// Mitsubishi GX Works2 project: PJT07_13_PLC(20220517_01)   PLC: Q03UDV

FUNCTION_BLOCK Alarm_FB
VAR_INPUT
  IB_Alarm : BOOL;  (* 入力@警報発生(0:-/1:発生) *)
END_VAR
VAR
  VT_AlarmDelayTimer : TIMER;  (* 内部@異常入力ﾃﾞｨﾚｲﾀｲﾏ *)
END_VAR
VAR_INPUT
  IW_DelayTimerVal : INT;  (* 入力@ﾃﾞｨﾚｲﾀｲﾏ値 *)
END_VAR
VAR_OUTPUT
  OB_AlarmHolding : BOOL;  (* 出力@ｱﾗｰﾑ自己保持(0:-/1:保持) *)
END_VAR
VAR_INPUT
  IB_AlarmResetPB : BOOL;  (* 入力@警報ﾘｾｯﾄPB(0:-/1:ﾘｾｯﾄ) *)
END_VAR
VAR
  VT_BuzzerStopTimer : TIMER;  (* 内部@ﾌﾞｻﾞｰｽﾄｯﾌﾟﾀｲﾏ *)
END_VAR
VAR_INPUT
  IW_BzStopTVal : INT;  (* 入力@ﾌﾞｻﾞｰｽﾄｯﾌﾟﾀｲﾏ値 *)
END_VAR
VAR
  VB_BuzzerStopFLG : BOOL;  (* 内部@ﾌﾞｻﾞｰｽﾄｯﾌﾟﾃﾞﾊﾞｲｽ(0:-/1:停止) *)
END_VAR
VAR_OUTPUT
  OB_DisplayFLG : BOOL;  (* 出力@ｱﾗｰﾑ表示ﾃﾞﾊﾞｲｽ(0:点滅/1:点灯) *)
END_VAR
VAR_INPUT
  IB_BuzzerStopPB : BOOL;  (* 入力@ﾌﾞｻﾞｰｽﾄｯﾌﾟPB(0:-/1:ｽﾄｯﾌﾟ) *)
END_VAR
VAR_OUTPUT
  OB_BuzzerFLG : BOOL;  (* 出力@ﾌﾞｻﾞｰﾌﾗｸﾞ *)
END_VAR
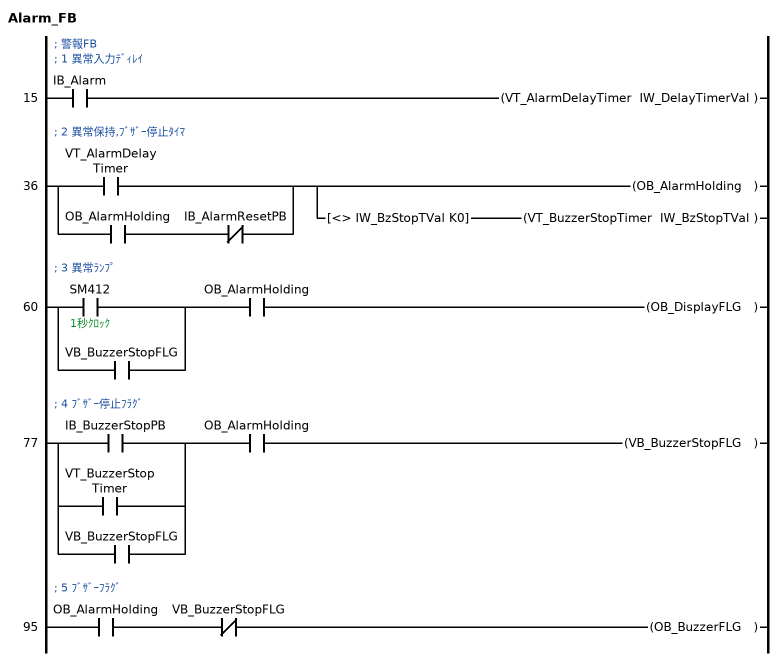
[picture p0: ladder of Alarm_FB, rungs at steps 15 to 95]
; 警報FB
; 1 異常入力ﾃﾞｨﾚｲ
15    LD      IB_Alarm
      OUT     VT_AlarmDelayTimer IW_DelayTimerVal
; 2 異常保持,ﾌﾞｻﾞｰ停止ﾀｲﾏ
36    LD      VT_AlarmDelayTimer
      LD      OB_AlarmHolding
      ANI     IB_AlarmResetPB
      ORB
      OUT     OB_AlarmHolding
      AND<>   IW_BzStopTVal K0
      OUT     VT_BuzzerStopTimer IW_BzStopTVal
; 3 異常ﾗﾝﾌﾟ
60    LD      SM412  ; 1秒ｸﾛｯｸ
      OR      VB_BuzzerStopFLG
      AND     OB_AlarmHolding
      OUT     OB_DisplayFLG
; 4 ﾌﾞｻﾞｰ停止ﾌﾗｸﾞ
77    LD      IB_BuzzerStopPB
      OR      VT_BuzzerStopTimer
      OR      VB_BuzzerStopFLG
      AND     OB_AlarmHolding
      OUT     VB_BuzzerStopFLG
; 5 ﾌﾞｻﾞｰﾌﾗｸﾞ
95    LD      OB_AlarmHolding
      ANI     VB_BuzzerStopFLG
      OUT     OB_BuzzerFLG
END_FUNCTION_BLOCK

PROGRAM 11_Alarm
VAR
  Alarm_FB_1 : Alarm_FB;
  Alarm_FB_2 : Alarm_FB;
END_VAR
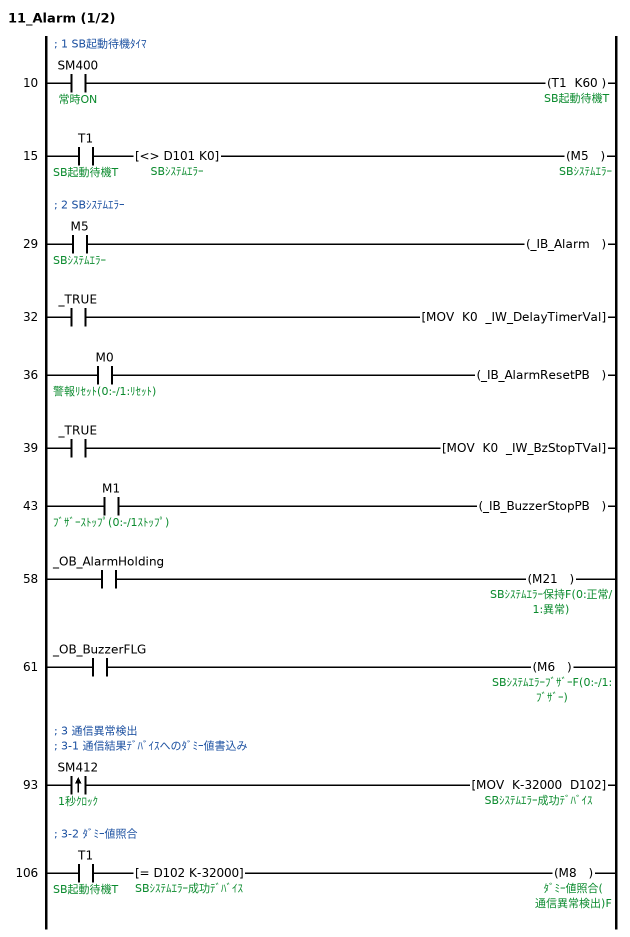
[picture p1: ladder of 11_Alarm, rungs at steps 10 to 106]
; 1 SB起動待機ﾀｲﾏ
10    LD      SM400  ; 常時ON
      OUT     T1 K60  ; SB起動待機T
15    LD      T1  ; SB起動待機T
      AND<>   D101 K0  ; SBｼｽﾃﾑｴﾗｰ
      OUT     M5  ; SBｼｽﾃﾑｴﾗｰ
; FB BLK START Alarm_FB(Alarm_FB_1)
; 2 SBｼｽﾃﾑｴﾗｰ
29    LD      M5  ; SBｼｽﾃﾑｴﾗｰ
      OUT     _IB_Alarm
32    LD      _TRUE
      MOV     K0 _IW_DelayTimerVal
36    LD      M0  ; 警報ﾘｾｯﾄ(0:-/1:ﾘｾｯﾄ)
      OUT     _IB_AlarmResetPB
39    LD      _TRUE
      MOV     K0 _IW_BzStopTVal
43    LD      M1  ; ﾌﾞｻﾞｰｽﾄｯﾌﾟ(0:-/1ｽﾄｯﾌﾟ)
      OUT     _IB_BuzzerStopPB
; FB START
; FB_NAME Alarm_FB
; INSTANCE_NAME Alarm_FB_1
; FB IN_B:IB_Alarm
; FB OUT_OB_AlarmHolding:B
; FB IN_W:IW_DelayTimerVal
; FB OUT_OB_DisplayFLG:B
; FB IN_B:IB_AlarmResetPB
; FB OUT_OB_BuzzerFLG:B
; FB IN_W:IW_BzStopTVal
; FB IN_B:IB_BuzzerStopPB
; FB END
58    LD      _OB_AlarmHolding
      OUT     M21  ; SBｼｽﾃﾑｴﾗｰ保持F(0:正常/1:異常)
61    LD      _OB_BuzzerFLG
      OUT     M6  ; SBｼｽﾃﾑｴﾗｰﾌﾞｻﾞｰF(0:-/1:ﾌﾞｻﾞｰ)
; FB BLK END
; 3 通信異常検出
; 3-1 通信結果ﾃﾞﾊﾞｲｽへのﾀﾞﾐｰ値書込み
93    LDP     SM412  ; 1秒ｸﾛｯｸ
      MOV     K-32000 D102  ; SBｼｽﾃﾑｴﾗｰ成功ﾃﾞﾊﾞｲｽ
; 3-2 ﾀﾞﾐｰ値照合
106   LD      T1  ; SB起動待機T
      AND=    D102 K-32000  ; SBｼｽﾃﾑｴﾗｰ成功ﾃﾞﾊﾞｲｽ
      OUT     M8  ; ﾀﾞﾐｰ値照合(通信異常検出)F
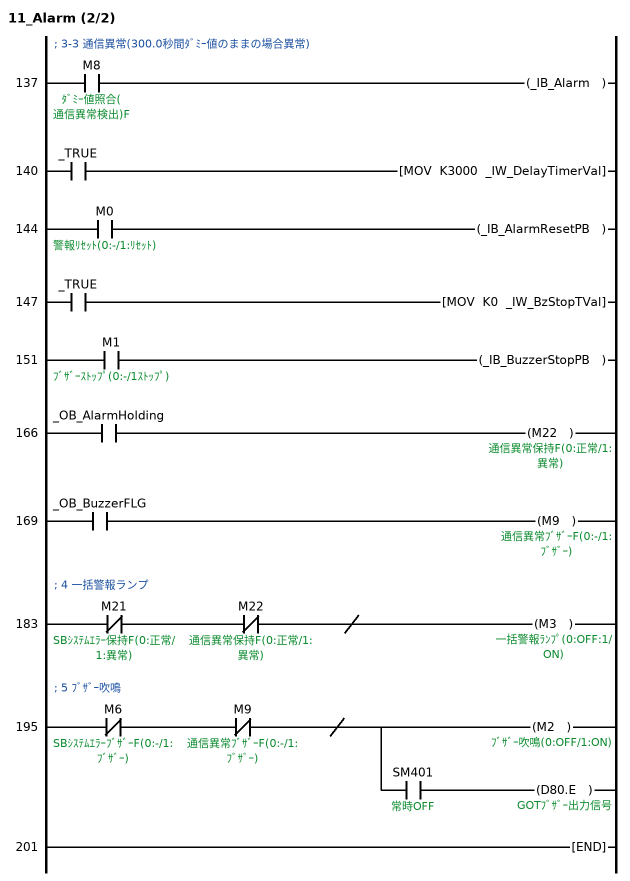
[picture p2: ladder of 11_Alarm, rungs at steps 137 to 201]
; FB BLK START Alarm_FB(Alarm_FB_2)
; 3-3 通信異常(300.0秒間ﾀﾞﾐｰ値のままの場合異常)
137   LD      M8  ; ﾀﾞﾐｰ値照合(通信異常検出)F
      OUT     _IB_Alarm
140   LD      _TRUE
      MOV     K3000 _IW_DelayTimerVal
144   LD      M0  ; 警報ﾘｾｯﾄ(0:-/1:ﾘｾｯﾄ)
      OUT     _IB_AlarmResetPB
147   LD      _TRUE
      MOV     K0 _IW_BzStopTVal
151   LD      M1  ; ﾌﾞｻﾞｰｽﾄｯﾌﾟ(0:-/1ｽﾄｯﾌﾟ)
      OUT     _IB_BuzzerStopPB
; FB START
; FB_NAME Alarm_FB
; INSTANCE_NAME Alarm_FB_2
; FB IN_B:IB_Alarm
; FB OUT_OB_AlarmHolding:B
; FB IN_W:IW_DelayTimerVal
; FB OUT_OB_DisplayFLG:B
; FB IN_B:IB_AlarmResetPB
; FB OUT_OB_BuzzerFLG:B
; FB IN_W:IW_BzStopTVal
; FB IN_B:IB_BuzzerStopPB
; FB END
166   LD      _OB_AlarmHolding
      OUT     M22  ; 通信異常保持F(0:正常/1:異常)
169   LD      _OB_BuzzerFLG
      OUT     M9  ; 通信異常ﾌﾞｻﾞｰF(0:-/1:ﾌﾞｻﾞｰ)
; FB BLK END
; 4 一括警報ランプ
183   LDI     M21  ; SBｼｽﾃﾑｴﾗｰ保持F(0:正常/1:異常)
      ANI     M22  ; 通信異常保持F(0:正常/1:異常)
      INV
      OUT     M3  ; 一括警報ﾗﾝﾌﾟ(0:OFF:1/ON)
; 5 ﾌﾞｻﾞｰ吹鳴
195   LDI     M6  ; SBｼｽﾃﾑｴﾗｰﾌﾞｻﾞｰF(0:-/1:ﾌﾞｻﾞｰ)
      ANI     M9  ; 通信異常ﾌﾞｻﾞｰF(0:-/1:ﾌﾞｻﾞｰ)
      INV
      OUT     M2  ; ﾌﾞｻﾞｰ吹鳴(0:OFF/1:ON)
      AND     SM401  ; 常時OFF
      OUT     D80.E  ; GOTﾌﾞｻﾞｰ出力信号
201   END
END_PROGRAM

PROGRAM 02_#2  // SB_Initial
VAR
  __IST_553ac48fffaf4984 : I+ST_553ac48fffaf4984;
END_VAR
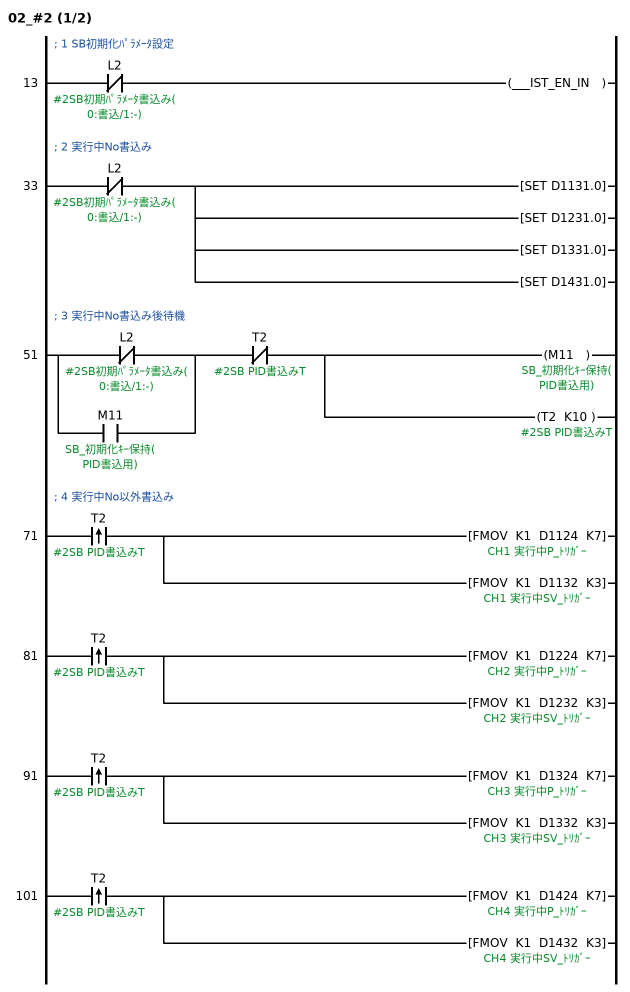
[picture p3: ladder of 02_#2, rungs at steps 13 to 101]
; FB BLK START I+ST_553ac48fffaf4984(__IST_553ac48fffaf4984)
; 1 SB初期化ﾊﾟﾗﾒｰﾀ設定
13    LDI     L2  ; #2SB初期ﾊﾟﾗﾒｰﾀ書込み(0:書込/1:-)
      OUT     ___IST_EN_IN
; FB START
; FB_NAME I+ST_553ac48fffaf4984
; INSTANCE_NAME __IST_553ac48fffaf4984
; FB IN_B:__IST_EN_IN
; FB OUT___IST_EN_OUT:B
; FB END
; FB BLK END
; 2 実行中No書込み
33    LDI     L2  ; #2SB初期ﾊﾟﾗﾒｰﾀ書込み(0:書込/1:-)
      SET     D1131.0
      SET     D1231.0
      SET     D1331.0
      SET     D1431.0
; 3 実行中No書込み後待機
51    LDI     L2  ; #2SB初期ﾊﾟﾗﾒｰﾀ書込み(0:書込/1:-)
      OR      M11  ; SB_初期化ｷｰ保持(PID書込用)
      ANI     T2  ; #2SB PID書込みT
      OUT     M11  ; SB_初期化ｷｰ保持(PID書込用)
      OUT     T2 K10  ; #2SB PID書込みT
; 4 実行中No以外書込み
71    LDP     T2  ; #2SB PID書込みT
      FMOV    K1 D1124 K7  ; CH1 実行中P_ﾄﾘｶﾞｰ
      FMOV    K1 D1132 K3  ; CH1 実行中SV_ﾄﾘｶﾞｰ
81    LDP     T2  ; #2SB PID書込みT
      FMOV    K1 D1224 K7  ; CH2 実行中P_ﾄﾘｶﾞｰ
      FMOV    K1 D1232 K3  ; CH2 実行中SV_ﾄﾘｶﾞｰ
91    LDP     T2  ; #2SB PID書込みT
      FMOV    K1 D1324 K7  ; CH3 実行中P_ﾄﾘｶﾞｰ
      FMOV    K1 D1332 K3  ; CH3 実行中SV_ﾄﾘｶﾞｰ
101   LDP     T2  ; #2SB PID書込みT
      FMOV    K1 D1424 K7  ; CH4 実行中P_ﾄﾘｶﾞｰ
      FMOV    K1 D1432 K3  ; CH4 実行中SV_ﾄﾘｶﾞｰ
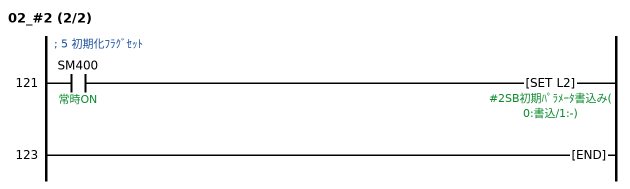
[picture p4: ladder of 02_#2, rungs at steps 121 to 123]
; 5 初期化ﾌﾗｸﾞｾｯﾄ
121   LD      SM400  ; 常時ON
      SET     L2  ; #2SB初期ﾊﾟﾗﾒｰﾀ書込み(0:書込/1:-)
123   END
END_PROGRAM

PROGRAM 22_#2  // SB100
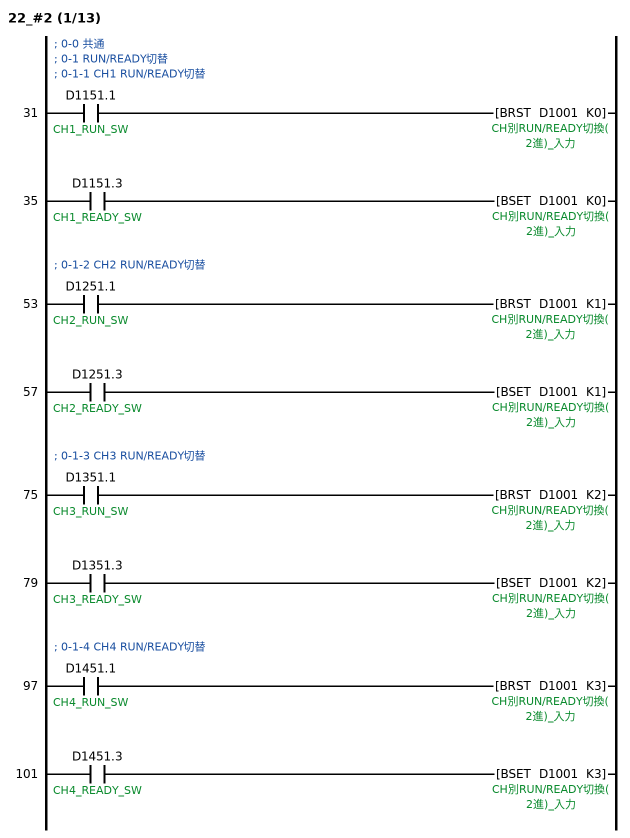
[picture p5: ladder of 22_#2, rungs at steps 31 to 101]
; 0-0 共通
; 0-1 RUN/READY切替
; 0-1-1 CH1 RUN/READY切替
31    LD      D1151.1  ; CH1_RUN_SW
      BRST    D1001 K0  ; CH別RUN/READY切換(2進)_入力
35    LD      D1151.3  ; CH1_READY_SW
      BSET    D1001 K0
; 0-1-2 CH2 RUN/READY切替
53    LD      D1251.1  ; CH2_RUN_SW
      BRST    D1001 K1
57    LD      D1251.3  ; CH2_READY_SW
      BSET    D1001 K1
; 0-1-3 CH3 RUN/READY切替
75    LD      D1351.1  ; CH3_RUN_SW
      BRST    D1001 K2
79    LD      D1351.3  ; CH3_READY_SW
      BSET    D1001 K2
; 0-1-4 CH4 RUN/READY切替
97    LD      D1451.1  ; CH4_RUN_SW
      BRST    D1001 K3
101   LD      D1451.3  ; CH4_READY_SW
      BSET    D1001 K3
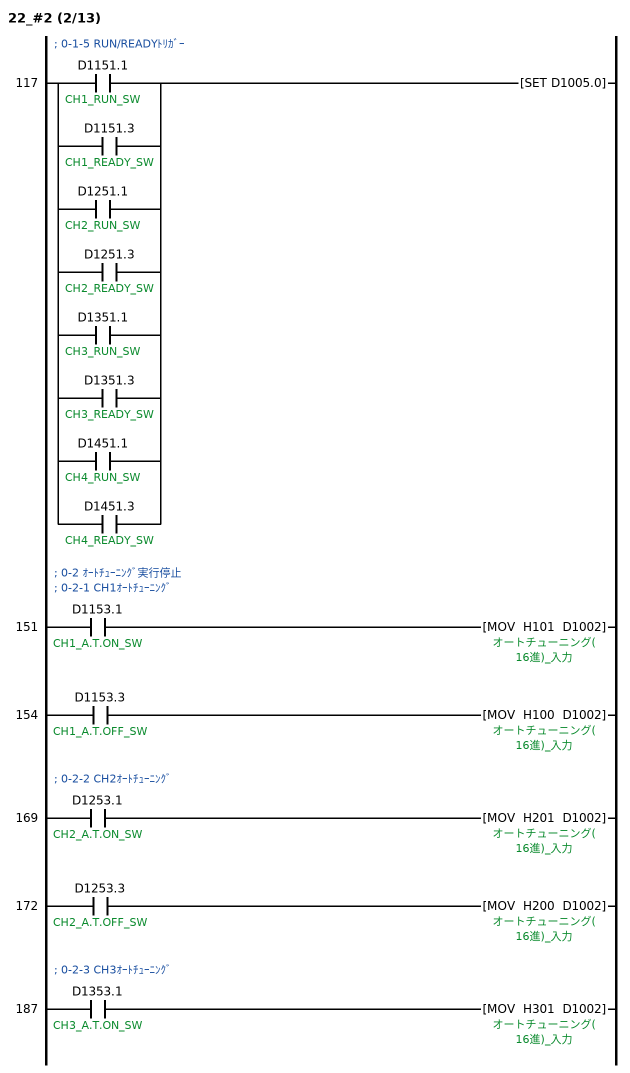
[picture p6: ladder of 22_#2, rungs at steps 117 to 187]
; 0-1-5 RUN/READYﾄﾘｶﾞｰ
117   LD      D1151.1  ; CH1_RUN_SW
      OR      D1151.3  ; CH1_READY_SW
      OR      D1251.1  ; CH2_RUN_SW
      OR      D1251.3  ; CH2_READY_SW
      OR      D1351.1  ; CH3_RUN_SW
      OR      D1351.3  ; CH3_READY_SW
      OR      D1451.1  ; CH4_RUN_SW
      OR      D1451.3  ; CH4_READY_SW
      SET     D1005.0
; 0-2 ｵｰﾄﾁｭｰﾆﾝｸﾞ実行停止
; 0-2-1 CH1ｵｰﾄﾁｭｰﾆﾝｸﾞ
151   LD      D1153.1  ; CH1_A.T.ON_SW
      MOV     H101 D1002  ; オートチューニング(16進)_入力
154   LD      D1153.3  ; CH1_A.T.OFF_SW
      MOV     H100 D1002
; 0-2-2 CH2ｵｰﾄﾁｭｰﾆﾝｸﾞ
169   LD      D1253.1  ; CH2_A.T.ON_SW
      MOV     H201 D1002
172   LD      D1253.3  ; CH2_A.T.OFF_SW
      MOV     H200 D1002
; 0-2-3 CH3ｵｰﾄﾁｭｰﾆﾝｸﾞ
187   LD      D1353.1  ; CH3_A.T.ON_SW
      MOV     H301 D1002
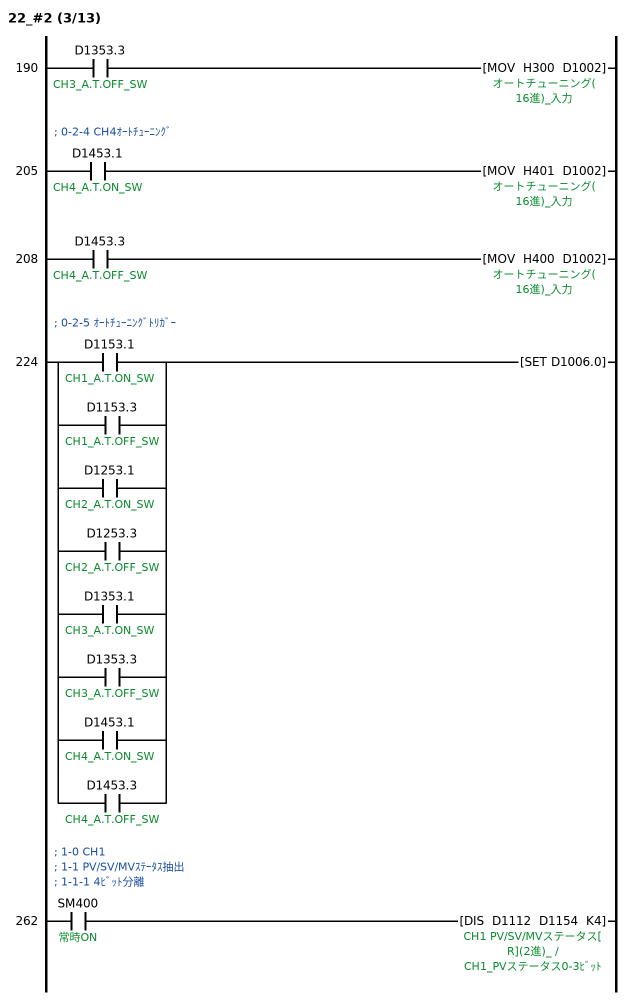
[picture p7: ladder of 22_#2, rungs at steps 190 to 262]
190   LD      D1353.3  ; CH3_A.T.OFF_SW
      MOV     H300 D1002
; 0-2-4 CH4ｵｰﾄﾁｭｰﾆﾝｸﾞ
205   LD      D1453.1  ; CH4_A.T.ON_SW
      MOV     H401 D1002
208   LD      D1453.3  ; CH4_A.T.OFF_SW
      MOV     H400 D1002
; 0-2-5 ｵｰﾄﾁｭｰﾆﾝｸﾞﾄﾘｶﾞｰ
224   LD      D1153.1  ; CH1_A.T.ON_SW
      OR      D1153.3  ; CH1_A.T.OFF_SW
      OR      D1253.1  ; CH2_A.T.ON_SW
      OR      D1253.3  ; CH2_A.T.OFF_SW
      OR      D1353.1  ; CH3_A.T.ON_SW
      OR      D1353.3  ; CH3_A.T.OFF_SW
      OR      D1453.1  ; CH4_A.T.ON_SW
      OR      D1453.3  ; CH4_A.T.OFF_SW
      SET     D1006.0
; 1-0 CH1
; 1-1 PV/SV/MVｽﾃｰﾀｽ抽出
; 1-1-1 4ﾋﾞｯﾄ分離
262   LD      SM400  ; 常時ON
      DIS     D1112 D1154 K4  ; CH1 PV/SV/MVステータス[R](2進)_ / CH1_PVステータス0-3ﾋﾞｯﾄ
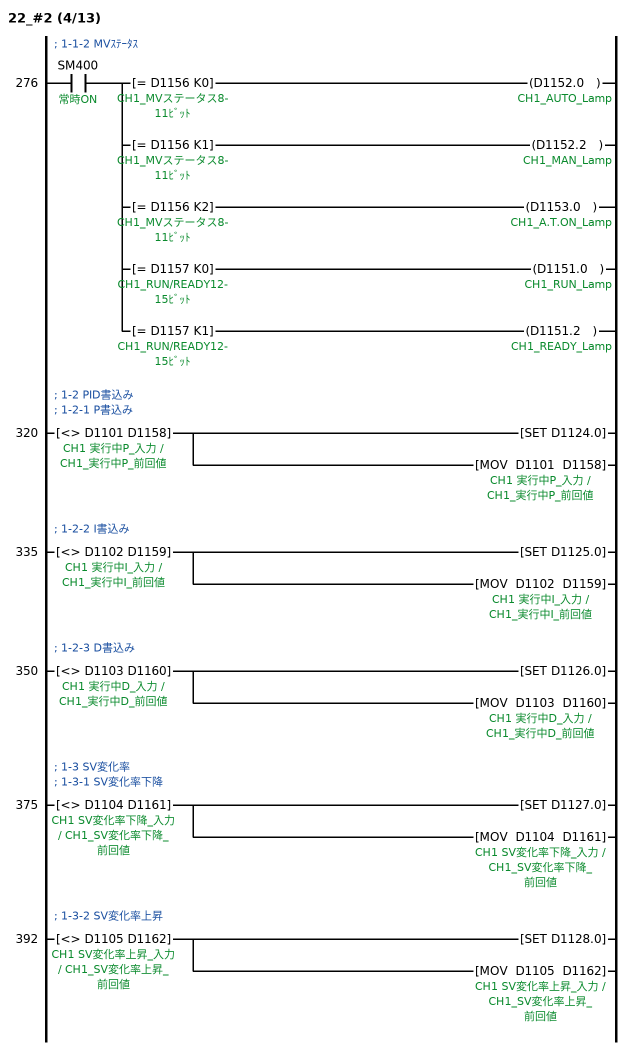
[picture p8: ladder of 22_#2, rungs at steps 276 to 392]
; 1-1-2 MVｽﾃｰﾀｽ
276   LD      SM400  ; 常時ON
      MPS
      AND=    D1156 K0  ; CH1_MVステータス8-11ﾋﾞｯﾄ
      OUT     D1152.0  ; CH1_AUTO_Lamp
      MRD
      AND=    D1156 K1  ; CH1_MVステータス8-11ﾋﾞｯﾄ
      OUT     D1152.2  ; CH1_MAN_Lamp
      MRD
      AND=    D1156 K2  ; CH1_MVステータス8-11ﾋﾞｯﾄ
      OUT     D1153.0  ; CH1_A.T.ON_Lamp
      MRD
      AND=    D1157 K0  ; CH1_RUN/READY12-15ﾋﾞｯﾄ
      OUT     D1151.0  ; CH1_RUN_Lamp
      MPP
      AND=    D1157 K1  ; CH1_RUN/READY12-15ﾋﾞｯﾄ
      OUT     D1151.2  ; CH1_READY_Lamp
; 1-2 PID書込み
; 1-2-1 P書込み
320   LD<>    D1101 D1158  ; CH1 実行中P_入力 / CH1_実行中P_前回値
      SET     D1124.0
      MOV     D1101 D1158
; 1-2-2 I書込み
335   LD<>    D1102 D1159  ; CH1 実行中I_入力 / CH1_実行中I_前回値
      SET     D1125.0
      MOV     D1102 D1159
; 1-2-3 D書込み
350   LD<>    D1103 D1160  ; CH1 実行中D_入力 / CH1_実行中D_前回値
      SET     D1126.0
      MOV     D1103 D1160
; 1-3 SV変化率
; 1-3-1 SV変化率下降
375   LD<>    D1104 D1161  ; CH1 SV変化率下降_入力 / CH1_SV変化率下降_前回値
      SET     D1127.0
      MOV     D1104 D1161
; 1-3-2 SV変化率上昇
392   LD<>    D1105 D1162  ; CH1 SV変化率上昇_入力 / CH1_SV変化率上昇_前回値
      SET     D1128.0
      MOV     D1105 D1162
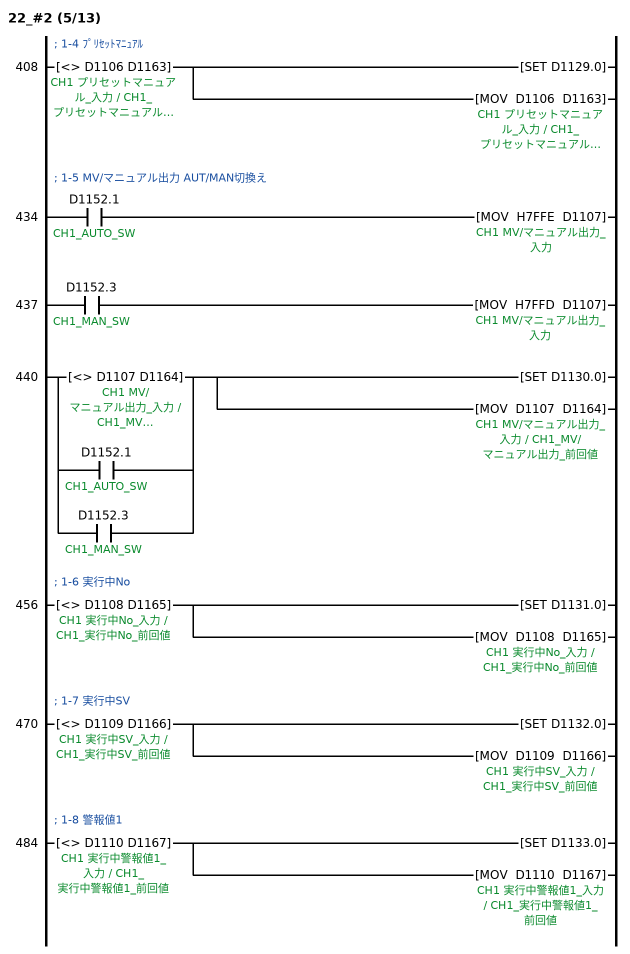
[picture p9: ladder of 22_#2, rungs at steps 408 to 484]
; 1-4 ﾌﾟﾘｾｯﾄﾏﾆｭｱﾙ
408   LD<>    D1106 D1163  ; CH1 プリセットマニュアル_入力 / CH1_プリセットマニュアル_前回値
      SET     D1129.0
      MOV     D1106 D1163
; 1-5 MV/マニュアル出力 AUT/MAN切換え
434   LD      D1152.1  ; CH1_AUTO_SW
      MOV     H7FFE D1107  ; CH1 MV/マニュアル出力_入力
437   LD      D1152.3  ; CH1_MAN_SW
      MOV     H7FFD D1107
440   LD<>    D1107 D1164  ; CH1 MV/マニュアル出力_入力 / CH1_MV/マニュアル出力_前回値
      OR      D1152.1  ; CH1_AUTO_SW
      OR      D1152.3  ; CH1_MAN_SW
      SET     D1130.0
      MOV     D1107 D1164
; 1-6 実行中No
456   LD<>    D1108 D1165  ; CH1 実行中No_入力 / CH1_実行中No_前回値
      SET     D1131.0
      MOV     D1108 D1165
; 1-7 実行中SV
470   LD<>    D1109 D1166  ; CH1 実行中SV_入力 / CH1_実行中SV_前回値
      SET     D1132.0
      MOV     D1109 D1166
; 1-8 警報値1
484   LD<>    D1110 D1167  ; CH1 実行中警報値1_入力 / CH1_実行中警報値1_前回値
      SET     D1133.0
      MOV     D1110 D1167
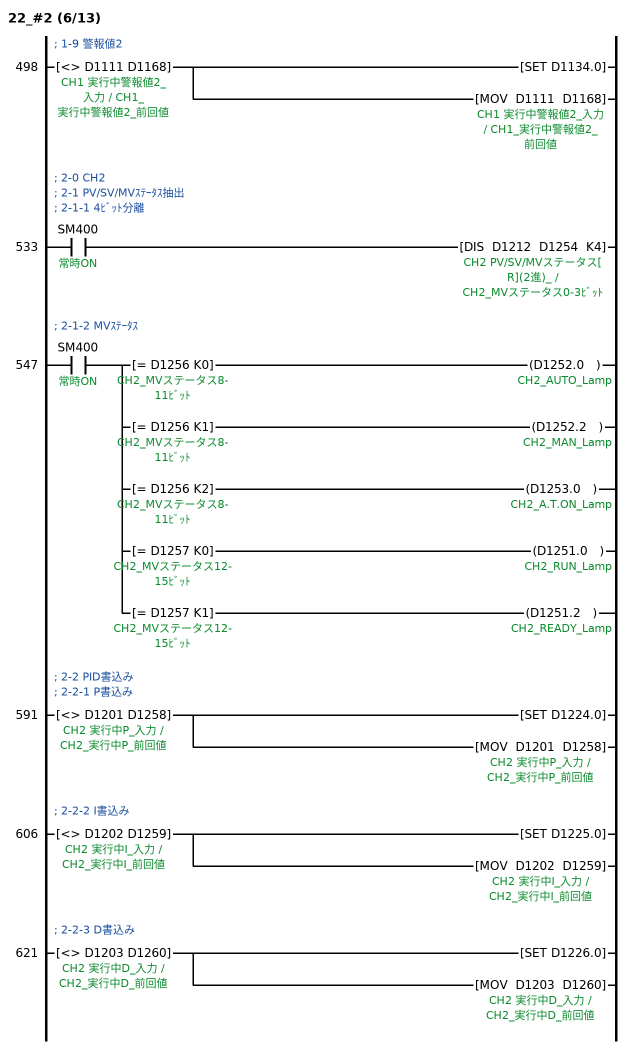
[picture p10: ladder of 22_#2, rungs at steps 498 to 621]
; 1-9 警報値2
498   LD<>    D1111 D1168  ; CH1 実行中警報値2_入力 / CH1_実行中警報値2_前回値
      SET     D1134.0
      MOV     D1111 D1168
; 2-0 CH2
; 2-1 PV/SV/MVｽﾃｰﾀｽ抽出
; 2-1-1 4ﾋﾞｯﾄ分離
533   LD      SM400  ; 常時ON
      DIS     D1212 D1254 K4  ; CH2 PV/SV/MVステータス[R](2進)_ / CH2_MVステータス0-3ﾋﾞｯﾄ
; 2-1-2 MVｽﾃｰﾀｽ
547   LD      SM400  ; 常時ON
      MPS
      AND=    D1256 K0  ; CH2_MVステータス8-11ﾋﾞｯﾄ
      OUT     D1252.0  ; CH2_AUTO_Lamp
      MRD
      AND=    D1256 K1  ; CH2_MVステータス8-11ﾋﾞｯﾄ
      OUT     D1252.2  ; CH2_MAN_Lamp
      MRD
      AND=    D1256 K2  ; CH2_MVステータス8-11ﾋﾞｯﾄ
      OUT     D1253.0  ; CH2_A.T.ON_Lamp
      MRD
      AND=    D1257 K0  ; CH2_MVステータス12-15ﾋﾞｯﾄ
      OUT     D1251.0  ; CH2_RUN_Lamp
      MPP
      AND=    D1257 K1  ; CH2_MVステータス12-15ﾋﾞｯﾄ
      OUT     D1251.2  ; CH2_READY_Lamp
; 2-2 PID書込み
; 2-2-1 P書込み
591   LD<>    D1201 D1258  ; CH2 実行中P_入力 / CH2_実行中P_前回値
      SET     D1224.0
      MOV     D1201 D1258
; 2-2-2 I書込み
606   LD<>    D1202 D1259  ; CH2 実行中I_入力 / CH2_実行中I_前回値
      SET     D1225.0
      MOV     D1202 D1259
; 2-2-3 D書込み
621   LD<>    D1203 D1260  ; CH2 実行中D_入力 / CH2_実行中D_前回値
      SET     D1226.0
      MOV     D1203 D1260
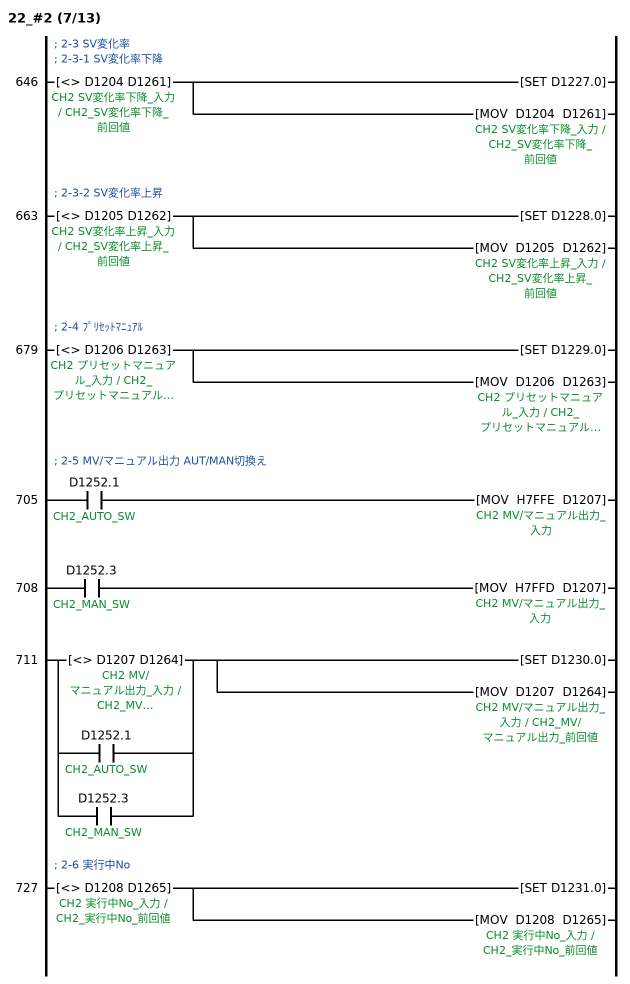
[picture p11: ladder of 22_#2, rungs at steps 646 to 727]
; 2-3 SV変化率
; 2-3-1 SV変化率下降
646   LD<>    D1204 D1261  ; CH2 SV変化率下降_入力 / CH2_SV変化率下降_前回値
      SET     D1227.0
      MOV     D1204 D1261
; 2-3-2 SV変化率上昇
663   LD<>    D1205 D1262  ; CH2 SV変化率上昇_入力 / CH2_SV変化率上昇_前回値
      SET     D1228.0
      MOV     D1205 D1262
; 2-4 ﾌﾟﾘｾｯﾄﾏﾆｭｱﾙ
679   LD<>    D1206 D1263  ; CH2 プリセットマニュアル_入力 / CH2_プリセットマニュアル_前回値
      SET     D1229.0
      MOV     D1206 D1263
; 2-5 MV/マニュアル出力 AUT/MAN切換え
705   LD      D1252.1  ; CH2_AUTO_SW
      MOV     H7FFE D1207  ; CH2 MV/マニュアル出力_入力
708   LD      D1252.3  ; CH2_MAN_SW
      MOV     H7FFD D1207
711   LD<>    D1207 D1264  ; CH2 MV/マニュアル出力_入力 / CH2_MV/マニュアル出力_前回値
      OR      D1252.1  ; CH2_AUTO_SW
      OR      D1252.3  ; CH2_MAN_SW
      SET     D1230.0
      MOV     D1207 D1264
; 2-6 実行中No
727   LD<>    D1208 D1265  ; CH2 実行中No_入力 / CH2_実行中No_前回値
      SET     D1231.0
      MOV     D1208 D1265
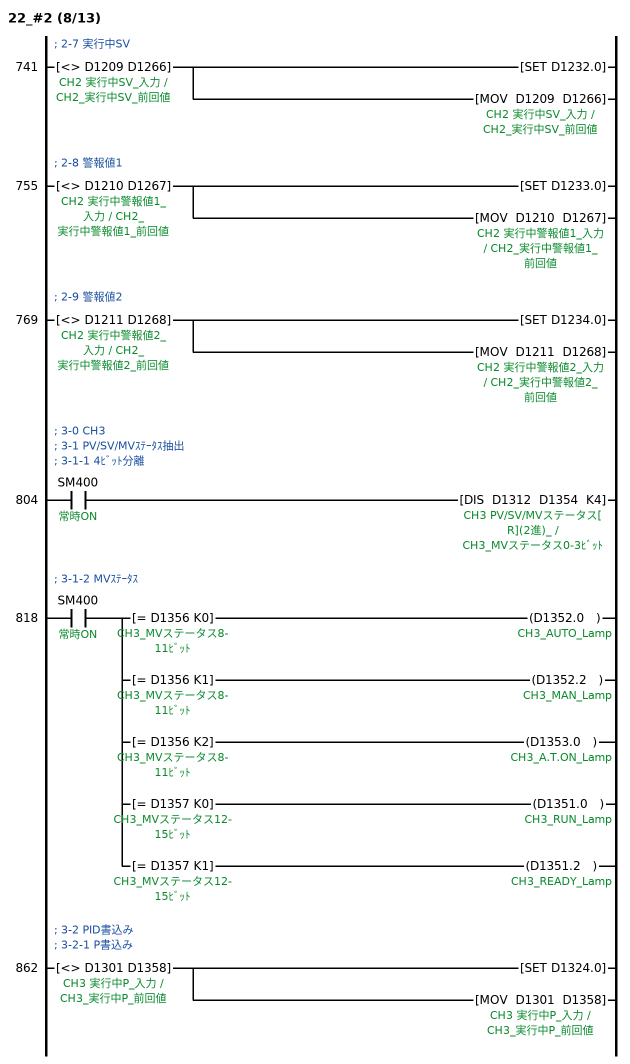
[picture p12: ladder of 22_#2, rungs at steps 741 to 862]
; 2-7 実行中SV
741   LD<>    D1209 D1266  ; CH2 実行中SV_入力 / CH2_実行中SV_前回値
      SET     D1232.0
      MOV     D1209 D1266
; 2-8 警報値1
755   LD<>    D1210 D1267  ; CH2 実行中警報値1_入力 / CH2_実行中警報値1_前回値
      SET     D1233.0
      MOV     D1210 D1267
; 2-9 警報値2
769   LD<>    D1211 D1268  ; CH2 実行中警報値2_入力 / CH2_実行中警報値2_前回値
      SET     D1234.0
      MOV     D1211 D1268
; 3-0 CH3
; 3-1 PV/SV/MVｽﾃｰﾀｽ抽出
; 3-1-1 4ﾋﾞｯﾄ分離
804   LD      SM400  ; 常時ON
      DIS     D1312 D1354 K4  ; CH3 PV/SV/MVステータス[R](2進)_ / CH3_MVステータス0-3ﾋﾞｯﾄ
; 3-1-2 MVｽﾃｰﾀｽ
818   LD      SM400  ; 常時ON
      MPS
      AND=    D1356 K0  ; CH3_MVステータス8-11ﾋﾞｯﾄ
      OUT     D1352.0  ; CH3_AUTO_Lamp
      MRD
      AND=    D1356 K1  ; CH3_MVステータス8-11ﾋﾞｯﾄ
      OUT     D1352.2  ; CH3_MAN_Lamp
      MRD
      AND=    D1356 K2  ; CH3_MVステータス8-11ﾋﾞｯﾄ
      OUT     D1353.0  ; CH3_A.T.ON_Lamp
      MRD
      AND=    D1357 K0  ; CH3_MVステータス12-15ﾋﾞｯﾄ
      OUT     D1351.0  ; CH3_RUN_Lamp
      MPP
      AND=    D1357 K1  ; CH3_MVステータス12-15ﾋﾞｯﾄ
      OUT     D1351.2  ; CH3_READY_Lamp
; 3-2 PID書込み
; 3-2-1 P書込み
862   LD<>    D1301 D1358  ; CH3 実行中P_入力 / CH3_実行中P_前回値
      SET     D1324.0
      MOV     D1301 D1358
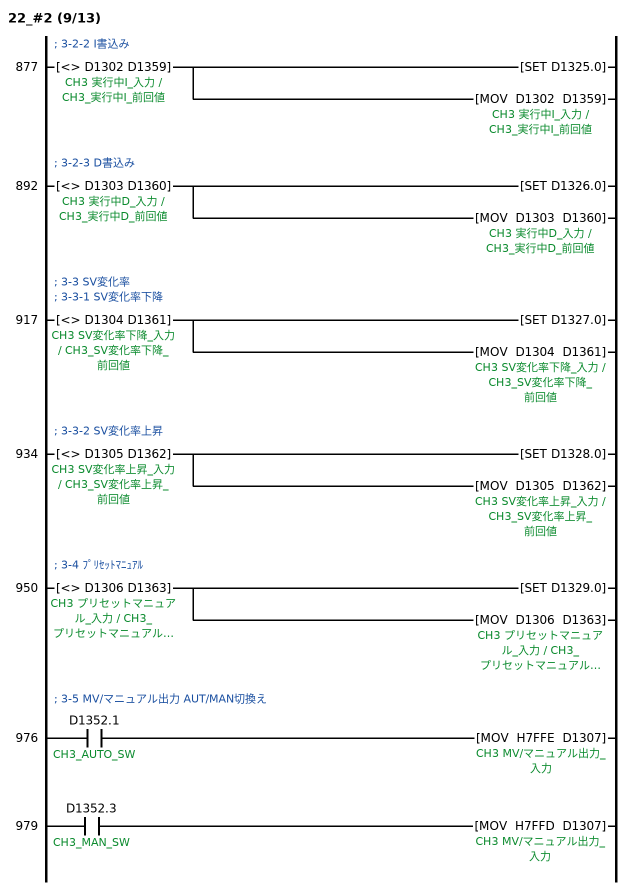
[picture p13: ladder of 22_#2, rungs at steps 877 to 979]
; 3-2-2 I書込み
877   LD<>    D1302 D1359  ; CH3 実行中I_入力 / CH3_実行中I_前回値
      SET     D1325.0
      MOV     D1302 D1359
; 3-2-3 D書込み
892   LD<>    D1303 D1360  ; CH3 実行中D_入力 / CH3_実行中D_前回値
      SET     D1326.0
      MOV     D1303 D1360
; 3-3 SV変化率
; 3-3-1 SV変化率下降
917   LD<>    D1304 D1361  ; CH3 SV変化率下降_入力 / CH3_SV変化率下降_前回値
      SET     D1327.0
      MOV     D1304 D1361
; 3-3-2 SV変化率上昇
934   LD<>    D1305 D1362  ; CH3 SV変化率上昇_入力 / CH3_SV変化率上昇_前回値
      SET     D1328.0
      MOV     D1305 D1362
; 3-4 ﾌﾟﾘｾｯﾄﾏﾆｭｱﾙ
950   LD<>    D1306 D1363  ; CH3 プリセットマニュアル_入力 / CH3_プリセットマニュアル_前回値
      SET     D1329.0
      MOV     D1306 D1363
; 3-5 MV/マニュアル出力 AUT/MAN切換え
976   LD      D1352.1  ; CH3_AUTO_SW
      MOV     H7FFE D1307  ; CH3 MV/マニュアル出力_入力
979   LD      D1352.3  ; CH3_MAN_SW
      MOV     H7FFD D1307
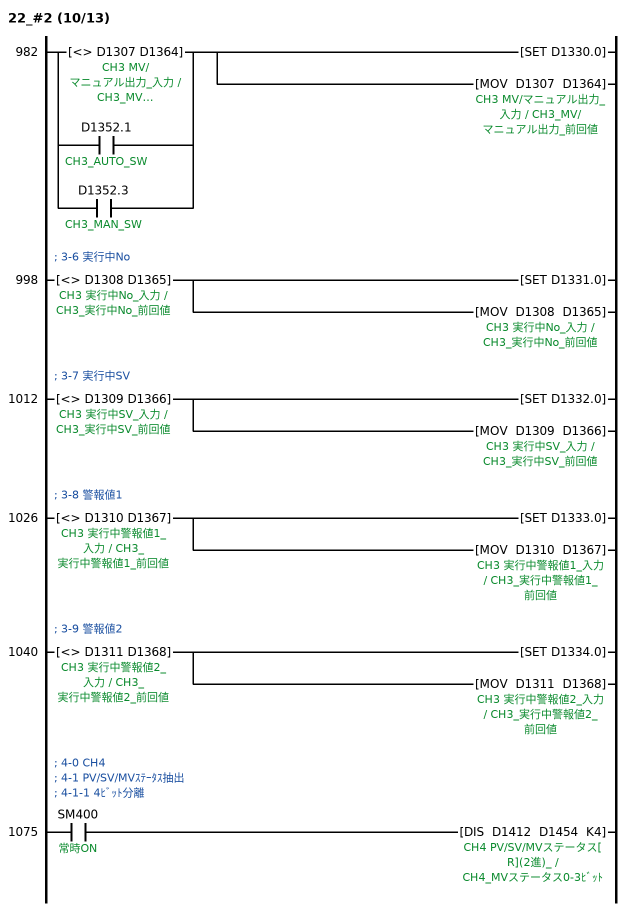
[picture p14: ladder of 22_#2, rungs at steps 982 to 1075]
982   LD<>    D1307 D1364  ; CH3 MV/マニュアル出力_入力 / CH3_MV/マニュアル出力_前回値
      OR      D1352.1  ; CH3_AUTO_SW
      OR      D1352.3  ; CH3_MAN_SW
      SET     D1330.0
      MOV     D1307 D1364
; 3-6 実行中No
998   LD<>    D1308 D1365  ; CH3 実行中No_入力 / CH3_実行中No_前回値
      SET     D1331.0
      MOV     D1308 D1365
; 3-7 実行中SV
1012  LD<>    D1309 D1366  ; CH3 実行中SV_入力 / CH3_実行中SV_前回値
      SET     D1332.0
      MOV     D1309 D1366
; 3-8 警報値1
1026  LD<>    D1310 D1367  ; CH3 実行中警報値1_入力 / CH3_実行中警報値1_前回値
      SET     D1333.0
      MOV     D1310 D1367
; 3-9 警報値2
1040  LD<>    D1311 D1368  ; CH3 実行中警報値2_入力 / CH3_実行中警報値2_前回値
      SET     D1334.0
      MOV     D1311 D1368
; 4-0 CH4
; 4-1 PV/SV/MVｽﾃｰﾀｽ抽出
; 4-1-1 4ﾋﾞｯﾄ分離
1075  LD      SM400  ; 常時ON
      DIS     D1412 D1454 K4  ; CH4 PV/SV/MVステータス[R](2進)_ / CH4_MVステータス0-3ﾋﾞｯﾄ
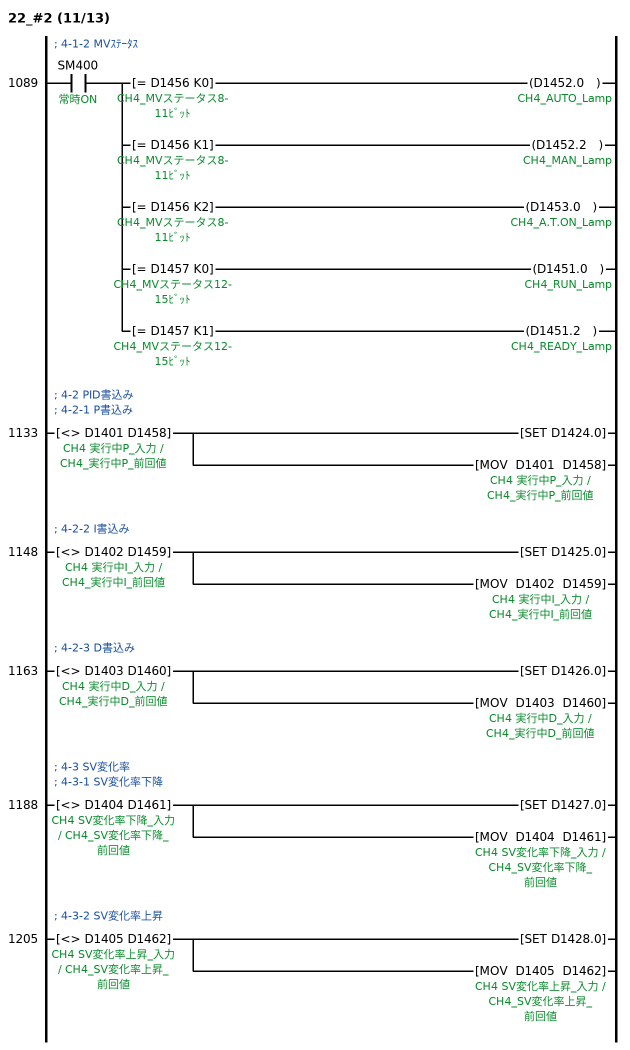
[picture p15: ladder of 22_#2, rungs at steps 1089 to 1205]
; 4-1-2 MVｽﾃｰﾀｽ
1089  LD      SM400  ; 常時ON
      MPS
      AND=    D1456 K0  ; CH4_MVステータス8-11ﾋﾞｯﾄ
      OUT     D1452.0  ; CH4_AUTO_Lamp
      MRD
      AND=    D1456 K1  ; CH4_MVステータス8-11ﾋﾞｯﾄ
      OUT     D1452.2  ; CH4_MAN_Lamp
      MRD
      AND=    D1456 K2  ; CH4_MVステータス8-11ﾋﾞｯﾄ
      OUT     D1453.0  ; CH4_A.T.ON_Lamp
      MRD
      AND=    D1457 K0  ; CH4_MVステータス12-15ﾋﾞｯﾄ
      OUT     D1451.0  ; CH4_RUN_Lamp
      MPP
      AND=    D1457 K1  ; CH4_MVステータス12-15ﾋﾞｯﾄ
      OUT     D1451.2  ; CH4_READY_Lamp
; 4-2 PID書込み
; 4-2-1 P書込み
1133  LD<>    D1401 D1458  ; CH4 実行中P_入力 / CH4_実行中P_前回値
      SET     D1424.0
      MOV     D1401 D1458
; 4-2-2 I書込み
1148  LD<>    D1402 D1459  ; CH4 実行中I_入力 / CH4_実行中I_前回値
      SET     D1425.0
      MOV     D1402 D1459
; 4-2-3 D書込み
1163  LD<>    D1403 D1460  ; CH4 実行中D_入力 / CH4_実行中D_前回値
      SET     D1426.0
      MOV     D1403 D1460
; 4-3 SV変化率
; 4-3-1 SV変化率下降
1188  LD<>    D1404 D1461  ; CH4 SV変化率下降_入力 / CH4_SV変化率下降_前回値
      SET     D1427.0
      MOV     D1404 D1461
; 4-3-2 SV変化率上昇
1205  LD<>    D1405 D1462  ; CH4 SV変化率上昇_入力 / CH4_SV変化率上昇_前回値
      SET     D1428.0
      MOV     D1405 D1462
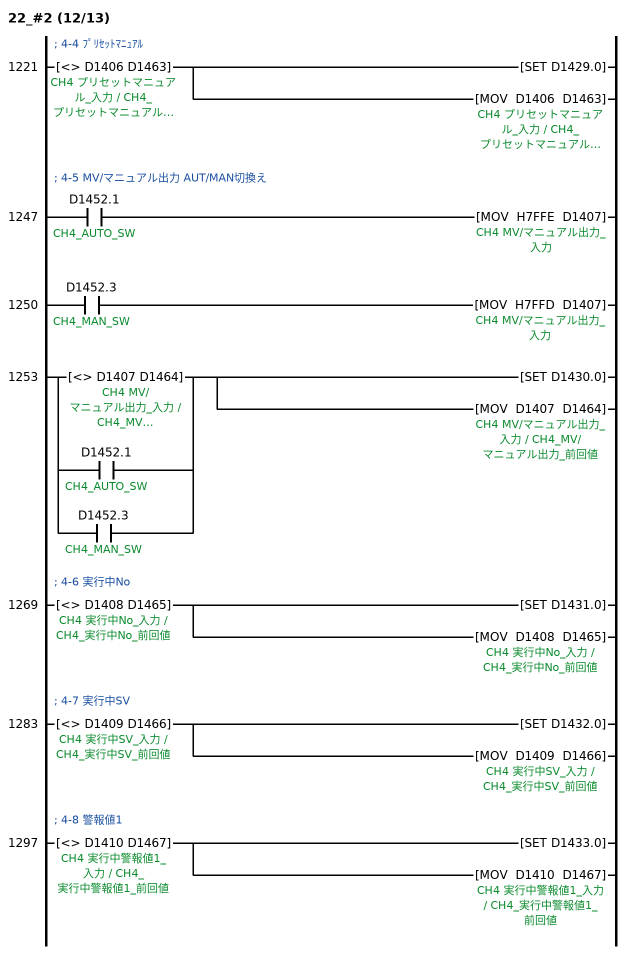
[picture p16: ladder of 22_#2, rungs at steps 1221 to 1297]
; 4-4 ﾌﾟﾘｾｯﾄﾏﾆｭｱﾙ
1221  LD<>    D1406 D1463  ; CH4 プリセットマニュアル_入力 / CH4_プリセットマニュアル_前回値
      SET     D1429.0
      MOV     D1406 D1463
; 4-5 MV/マニュアル出力 AUT/MAN切換え
1247  LD      D1452.1  ; CH4_AUTO_SW
      MOV     H7FFE D1407  ; CH4 MV/マニュアル出力_入力
1250  LD      D1452.3  ; CH4_MAN_SW
      MOV     H7FFD D1407
1253  LD<>    D1407 D1464  ; CH4 MV/マニュアル出力_入力 / CH4_MV/マニュアル出力_前回値
      OR      D1452.1  ; CH4_AUTO_SW
      OR      D1452.3  ; CH4_MAN_SW
      SET     D1430.0
      MOV     D1407 D1464
; 4-6 実行中No
1269  LD<>    D1408 D1465  ; CH4 実行中No_入力 / CH4_実行中No_前回値
      SET     D1431.0
      MOV     D1408 D1465
; 4-7 実行中SV
1283  LD<>    D1409 D1466  ; CH4 実行中SV_入力 / CH4_実行中SV_前回値
      SET     D1432.0
      MOV     D1409 D1466
; 4-8 警報値1
1297  LD<>    D1410 D1467  ; CH4 実行中警報値1_入力 / CH4_実行中警報値1_前回値
      SET     D1433.0
      MOV     D1410 D1467
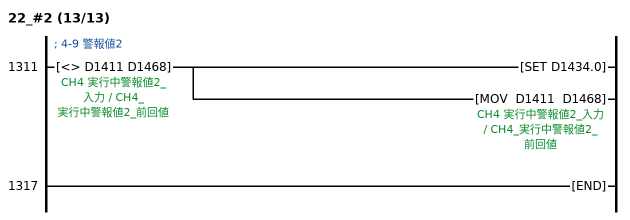
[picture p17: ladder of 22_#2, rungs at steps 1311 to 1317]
; 4-9 警報値2
1311  LD<>    D1411 D1468  ; CH4 実行中警報値2_入力 / CH4_実行中警報値2_前回値
      SET     D1434.0
      MOV     D1411 D1468
1317  END
END_PROGRAM

FUNCTION_BLOCK I+ST_553ac48fffaf4984
VAR_INPUT
  __IST_EN_IN : BOOL;
END_VAR
VAR_OUTPUT
  __IST_EN_OUT : BOOL;
END_VAR
(* IST HEADER START *)
IF NOT __IST_EN_IN THEN __IST_EN_OUT:=FALSE; RETURN; END_IF;
(* VERSION=1:TYPE=STB *)
(* IST HEADER END *)
D1101:=50;		(*CH1 実行中P*)
D1102:=60;		(*CH1 実行中I*)
D1103:=30;		(*CH1 実行中D*)
D1104:=0;		(*CH1 SV変化率下降*)
D1105:=0;		(*CH1 SV変化率上昇*)
D1106:=0;		(*CH1 プリセットマニュアル*)
D1108:=1;		(*CH1 実行中No*)
D1109:=234;		(*CH1 実行中SV*)
D1110:=30000;	(*CH1 実行中警報値1*)
D1111:=-30000;	(*CH1 実行中警報値2*)
D1201:=50;		(*CH2 実行中P*)
D1202:=60;		(*CH2 実行中I*)
D1203:=30;		(*CH2 実行中D*)
D1204:=0;		(*CH2 SV変化率下降*)
D1205:=0;		(*CH2 SV変化率上昇*)
D1206:=0;		(*CH2 プリセットマニュアル*)
D1208:=1;		(*CH2 実行中No*)
D1209:=234;		(*CH2 実行中SV*)
D1210:=30000;	(*CH2 実行中警報値1*)
D1211:=-30000;	(*CH2 実行中警報値2*)
D1301:=50;		(*CH3 実行中P*)
D1302:=60;		(*CH3 実行中I*)
D1303:=30;		(*CH3 実行中D*)
D1304:=0;		(*CH3 SV変化率下降*)
D1305:=0;		(*CH3 SV変化率上昇*)
D1306:=0;		(*CH3 プリセットマニュアル*)
D1308:=1;		(*CH3 実行中No*)
D1309:=234;		(*CH3 実行中SV*)
D1310:=30000;	(*CH3 実行中警報値1*)
D1311:=-30000;	(*CH3 実行中警報値2*)
D1401:=50;		(*CH4 実行中P*)
D1402:=60;		(*CH4 実行中I*)
D1403:=30;		(*CH4 実行中D*)
D1404:=0;		(*CH4 SV変化率下降*)
D1405:=0;		(*CH4 SV変化率上昇*)
D1406:=0;		(*CH4 プリセットマニュアル*)
D1408:=1;		(*CH4 実行中No*)
D1409:=234;		(*CH4 実行中SV*)
D1410:=30000;	(*CH4 実行中警報値1*)
D1411:=-30000;(*CH4 実行中警報値2*)
END_FUNCTION_BLOCK

PROGRAM 01_SB  // Initial
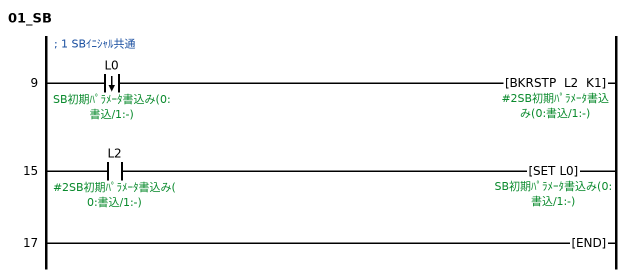
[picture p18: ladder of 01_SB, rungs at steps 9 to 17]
; 1 SBｲﾆｼｬﾙ共通
9     LDF     L0  ; SB初期ﾊﾟﾗﾒｰﾀ書込み(0:書込/1:-)
      BKRSTP  L2 K1  ; #2SB初期ﾊﾟﾗﾒｰﾀ書込み(0:書込/1:-)
15    LD      L2  ; #2SB初期ﾊﾟﾗﾒｰﾀ書込み(0:書込/1:-)
      SET     L0  ; SB初期ﾊﾟﾗﾒｰﾀ書込み(0:書込/1:-)
17    END
END_PROGRAM

// device comments not shown above
D71  ; GOTﾍﾞｰｽ画面
D72  ; GOTｵｰﾊﾞｰﾗｯﾌﾟｳｨﾝﾄﾞｳ
D73  ; GOTｽｰﾊﾟｰｲﾝﾎﾟｰｽﾞｳｨﾝﾄﾞｳ
D80  ; GOTｼｽﾃﾑ信号1-1
D81  ; GOTｼｽﾃﾑ信号2-1
D82  ; GOT数値入力番号
D83  ; GOT数値入力変更前値(32ﾋﾞｯﾄ)
D84  ; GOT数値入力変更前値(32ﾋﾞｯﾄ)
D85  ; GOT数値入力変更後値(32ﾋﾞｯﾄ)
D86  ; GOT数値入力変更後値(32ﾋﾞｯﾄ)
D87  ; GOTｴﾗｰｺｰﾄﾞ
D88  ; GOTｴﾗｰｺｰﾄﾞ2
D89  ; GOT印字中ﾚﾎﾟｰﾄ画面番号
D90  ; GOT表示中ﾍﾞｰｽ画面番号
D91  ; GOT表示中ｳｨﾝﾄﾞｳ1画面番号
D92  ; GOT現在ｶｰｿﾙ表示ｵﾌﾞｼﾞｪｸﾄID
D93  ; GOT前回ｶｰｿﾙ表示ｵﾌﾞｼﾞｪｸﾄID
D94  ; GOT現在ｶｰｿﾙ表示ﾕｰｻﾞID
D95  ; GOT前回ｶｰｿﾙ表示ﾕｰｻﾞID
D96  ; GOT入力ｷｰｺｰﾄﾞ
D97  ; GOT外部入出力機能･入力情報1
D98  ; GOT外部入出力機能･入力情報2
D103  ; SBｼｽﾃﾑｴﾗｰ失敗ﾃﾞﾊﾞｲｽ
D104  ; SBｼｽﾃﾑｴﾗｰｴﾗｰﾃﾞﾊﾞｲｽ
D1003  ; CH別RUN/READY切換(2進)_表示
D1004  ; オートチューニング(16進)_表示
D1005  ; CH別RUN/READY切換(2進)_ﾄﾘｶﾞｰ
D1006  ; オートチューニング(16進)_ﾄﾘｶﾞｰ
D1011  ; CH1PV_表示
D1012  ; CH2PV_表示
D1013  ; CH3PV_表示
D1014  ; CH4PV_表示
D1015  ; CH1SV_表示
D1016  ; CH2SV_表示
D1017  ; CH3SV_表示
D1018  ; CH4SV_表示
D1019  ; CH1MV_表示
D1020  ; CH2MV_表示
D1021  ; CH3MV_表示
D1022  ; CH4MV_表示
D1023  ; ALステータス1_表示
D1024  ; ALステータス2_表示
D1113  ; CH1 実行中P_表示
D1114  ; CH1 実行中I_表示
D1115  ; CH1 実行中D_表示
D1116  ; CH1 SV変化率下降_表示
D1117  ; CH1 SV変化率上昇_表示
D1118  ; CH1 プリセットマニュアル_表示
D1119  ; CH1 MV/マニュアル出力_表示
D1120  ; CH1 実行中No_表示
D1121  ; CH1 実行中SV_表示
D1122  ; CH1 実行中警報値1_表示
D1123  ; CH1 実行中警報値2_表示
D1125  ; CH1 実行中I_ﾄﾘｶﾞｰ
D1126  ; CH1 実行中D_ﾄﾘｶﾞｰ
D1127  ; CH1 SV変化率下降_ﾄﾘｶﾞｰ
D1128  ; CH1 SV変化率上昇_ﾄﾘｶﾞｰ
D1129  ; CH1 プリセットマニュアル_ﾄﾘｶﾞｰ
D1130  ; CH1 MV/マニュアル出力_ﾄﾘｶﾞｰ
D1131  ; CH1 実行中No_ﾄﾘｶﾞｰ
D1133  ; CH1 実行中警報値1_ﾄﾘｶﾞｰ
D1134  ; CH1 実行中警報値2_ﾄﾘｶﾞｰ
D1151  ; CH1_RUNREADY
D1152  ; CH1_AUTOMAN
D1153  ; CH1_A.T
D1155  ; CH1_SVステータス4-7ﾋﾞｯﾄ
D1213  ; CH2 実行中P_表示
D1214  ; CH2 実行中I_表示
D1215  ; CH2 実行中D_表示
D1216  ; CH2 SV変化率下降_表示
D1217  ; CH2 SV変化率上昇_表示
D1218  ; CH2 プリセットマニュアル_表示
D1219  ; CH2 MV/マニュアル出力_表示
D1220  ; CH2 実行中No_表示
D1221  ; CH2 実行中SV_表示
D1222  ; CH2 実行中警報値1_表示
D1223  ; CH2 実行中警報値2_表示
D1225  ; CH2 実行中I_ﾄﾘｶﾞｰ
D1226  ; CH2 実行中D_ﾄﾘｶﾞｰ
D1227  ; CH2 SV変化率下降_ﾄﾘｶﾞｰ
D1228  ; CH2 SV変化率上昇_ﾄﾘｶﾞｰ
D1229  ; CH2 プリセットマニュアル_ﾄﾘｶﾞｰ
D1230  ; CH2 MV/マニュアル出力_ﾄﾘｶﾞｰ
D1231  ; CH2 実行中No_ﾄﾘｶﾞｰ
D1233  ; CH2 実行中警報値1_ﾄﾘｶﾞｰ
D1234  ; CH2 実行中警報値2_ﾄﾘｶﾞｰ
D1251  ; CH2_RUNREADY
D1252  ; CH2_AUTOMAN
D1253  ; CH2_A.T
D1255  ; CH2_MVステータス4-7ﾋﾞｯﾄ
D1313  ; CH3 実行中P_表示
D1314  ; CH3 実行中I_表示
D1315  ; CH3 実行中D_表示
D1316  ; CH3 SV変化率下降_表示
D1317  ; CH3 SV変化率上昇_表示
D1318  ; CH3 プリセットマニュアル_表示
D1319  ; CH3 MV/マニュアル出力_表示
D1320  ; CH3 実行中No_表示
D1321  ; CH3 実行中SV_表示
D1322  ; CH3 実行中警報値1_表示
D1323  ; CH3 実行中警報値2_表示
D1325  ; CH3 実行中I_ﾄﾘｶﾞｰ
D1326  ; CH3 実行中D_ﾄﾘｶﾞｰ
D1327  ; CH3 SV変化率下降_ﾄﾘｶﾞｰ
D1328  ; CH3 SV変化率上昇_ﾄﾘｶﾞｰ
D1329  ; CH3 プリセットマニュアル_ﾄﾘｶﾞｰ
D1330  ; CH3 MV/マニュアル出力_ﾄﾘｶﾞｰ
D1331  ; CH3 実行中No_ﾄﾘｶﾞｰ
D1333  ; CH3 実行中警報値1_ﾄﾘｶﾞｰ
D1334  ; CH3 実行中警報値2_ﾄﾘｶﾞｰ
D1351  ; CH3_RUNREADY
D1352  ; CH3_AUTOMAN
D1353  ; CH3_A.T
D1355  ; CH3_MVステータス4-7ﾋﾞｯﾄ
D1413  ; CH4 実行中P_表示
D1414  ; CH4 実行中I_表示
D1415  ; CH4 実行中D_表示
D1416  ; CH4 SV変化率下降_表示
D1417  ; CH4 SV変化率上昇_表示
D1418  ; CH4 プリセットマニュアル_表示
D1419  ; CH4 MV/マニュアル出力_表示
D1420  ; CH4 実行中No_表示
D1421  ; CH4 実行中SV_表示
D1422  ; CH4 実行中警報値1_表示
D1423  ; CH4 実行中警報値2_表示
D1425  ; CH4 実行中I_ﾄﾘｶﾞｰ
D1426  ; CH4 実行中D_ﾄﾘｶﾞｰ
D1427  ; CH4 SV変化率下降_ﾄﾘｶﾞｰ
D1428  ; CH4 SV変化率上昇_ﾄﾘｶﾞｰ
D1429  ; CH4 プリセットマニュアル_ﾄﾘｶﾞｰ
D1430  ; CH4 MV/マニュアル出力_ﾄﾘｶﾞｰ
D1431  ; CH4 実行中No_ﾄﾘｶﾞｰ
D1433  ; CH4 実行中警報値1_ﾄﾘｶﾞｰ
D1434  ; CH4 実行中警報値2_ﾄﾘｶﾞｰ
D1451  ; CH4_RUNREADY
D1452  ; CH4_AUTOMAN
D1453  ; CH4_A.T
D1455  ; CH4_MVステータス4-7ﾋﾞｯﾄ
D80.0  ; GOT自動ｽｸﾘｰﾝｾｰﾌﾞ無効信号
D80.1  ; GOT強制ｽｸﾘｰﾝｾｰﾌﾞ番号
D80.2  ; GOT強制ｽｸﾘｰﾝｾｰﾌﾞﾀｯﾁ解除信号
D80.3  ; GOT入力ｷｰ読出し完了信号
D80.4  ; GOT数値入力読出し完了信号
D80.5  ; GOTﾊﾞｰｺｰﾄﾞ入力無効信号(CH8)
D80.6  ; GOT外部機器入出力完了信号(CH8)
D80.7  ; GOT使用禁止
D80.8  ; GOTﾌﾞｻﾞｰｽﾘｰｼｮｯﾄ出力信号
D80.9  ; GOTﾀｯﾁ操作無効信号
D80.A  ; GOTﾊｰﾄﾞｺﾋﾟｰ設定有効信号
D80.B  ; GOT使用禁止
D80.C  ; GOTﾊｰﾄﾞｺﾋﾟｰ白黒反転信号
D80.D  ; GOTｴﾗｰﾘｾｯﾄ信号
D80.F  ; GOTﾌﾞｻﾞｰﾜﾝｼｮｯﾄ出力信号
D1023.0  ; CH1_AL1_表示
D1023.2  ; CH1_AL2_表示
D1023.4  ; CH1_AL3_表示
D1023.6  ; CH1_AL4_表示
D1023.8  ; CH2_AL1_表示
D1023.A  ; CH2_AL2_表示
D1023.C  ; CH2_AL3_表示
D1023.E  ; CH2_AL4_表示
D1024.0  ; CH3_AL1_表示
D1024.2  ; CH3_AL2_表示
D1024.4  ; CH3_AL3_表示
D1024.6  ; CH3_AL4_表示
D1024.8  ; CH4_AL1_表示
D1024.A  ; CH4_AL2_表示
D1024.C  ; CH4_AL3_表示
D1024.E  ; CH4_AL4_表示
D1153.2  ; CH1_A.T.OFF_Lamp
D1253.2  ; CH2_A.T.OFF_Lamp
D1353.2  ; CH3_A.T.OFF_Lamp
D1453.2  ; CH4_A.T.OFF_Lamp
